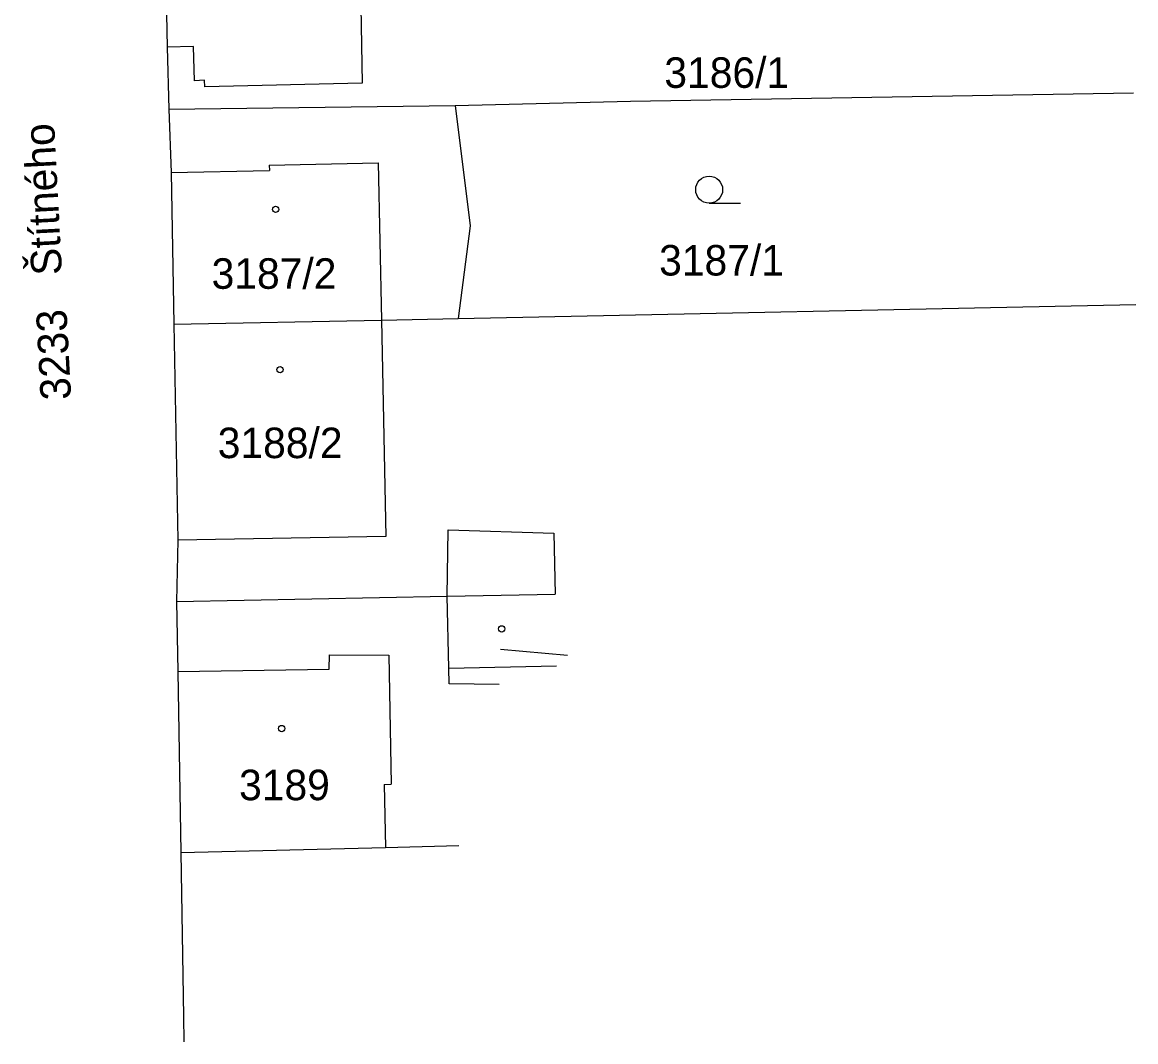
# Model space of a CAD drawing. Extents: x -738085 to -734306, y -1122197 to -1119753.
# Drawn here: x -734443.9 to -734381.9, y -1120299.5 to -1120242.7 of the extents above; entities that cross this region are included whole.
import ezdxf

# ---------------------------------------------------------------- set-up
doc = ezdxf.new("R2010")
doc.units = 0
for name, color, linetype in [('Hranice parcel', 7, 'Continuous'), ('Parcelní čísla', 7, 'Continuous'), ('Pop  PČ popisy', 7, 'Continuous'), ('Vnitřní kresba', 7, 'Continuous'), ('Značky budov', 7, 'Continuous'), ('Značky kultur', 7, 'Continuous')]:
    doc.layers.add(name, color=color, linetype=linetype)

msp = doc.modelspace()

# ---------------------------------------------------------------- linework, layer by layer
at = {"layer": 'Hranice parcel'}
for p, q in [((-734436.06, -1120234.59), (-734435.82, -1120244.07)), ((-734435.82, -1120244.07), (-734435.73, -1120247.52)), ((-734435.73, -1120247.52), (-734419.78, -1120247.33)), ((-734419.62, -1120259.19), (-734381.87, -1120258.4)), ((-734435.45, -1120259.5), (-734423.89, -1120259.28)), ((-734423.89, -1120259.28), (-734419.62, -1120259.19)), ((-734435.45, -1120259.5), (-734435.23, -1120271.53)), ((-734435.23, -1120271.53), (-734435.3, -1120274.95)), ((-734435.3, -1120274.95), (-734420.22, -1120274.65)), ((-734420.22, -1120274.65), (-734414.22, -1120274.53))]:
    msp.add_line(p, q, dxfattribs=at)
for points in [[(-734425.16, -1120234.37), (-734424.97, -1120246.07), (-734433.73, -1120246.29), (-734433.74, -1120245.92), (-734434.31, -1120245.94), (-734434.35, -1120244.04), (-734435.82, -1120244.07)], [(-734419.78, -1120247.33), (-734410.01, -1120247.08), (-734381.99, -1120246.61)], [(-734435.73, -1120247.52), (-734435.6, -1120251.05), (-734435.45, -1120259.5)], [(-734419.78, -1120247.33), (-734418.94, -1120254.02), (-734419.62, -1120259.19)], [(-734423.89, -1120259.28), (-734423.65, -1120271.32), (-734435.23, -1120271.53)], [(-734417.33, -1120279.57), (-734420.12, -1120279.52), (-734420.14, -1120278.65), (-734420.22, -1120274.65)], [(-734435.3, -1120274.95), (-734435.24, -1120278.84), (-734435.07, -1120288.93)], [(-734435.07, -1120288.93), (-734423.67, -1120288.65), (-734419.57, -1120288.53)], [(-734435.07, -1120288.93), (-734434.91, -1120298.05), (-734434.89, -1120299.46)]]:
    msp.add_lwpolyline(points, dxfattribs=at)
at = {"layer": 'Pop  PČ popisy'}
msp.add_line((-734417.26, -1120277.6), (-734413.53, -1120277.94), dxfattribs=at)
at = {"layer": 'Vnitřní kresba'}
for p, q in [((-734430.14, -1120250.64), (-734424.07, -1120250.52)), ((-734430.14, -1120250.64), (-734430.13, -1120250.94)), ((-734424.07, -1120250.52), (-734423.89, -1120259.28)), ((-734435.6, -1120251.05), (-734430.13, -1120250.94)), ((-734420.22, -1120274.65), (-734420.17, -1120270.95)), ((-734420.17, -1120270.95), (-734414.29, -1120271.14)), ((-734414.29, -1120271.14), (-734414.22, -1120274.53)), ((-734426.8, -1120278.71), (-734426.79, -1120277.91)), ((-734426.79, -1120277.91), (-734423.48, -1120277.94)), ((-734423.48, -1120277.94), (-734423.35, -1120285.12)), ((-734420.14, -1120278.65), (-734414.14, -1120278.53)), ((-734435.24, -1120278.84), (-734426.8, -1120278.71)), ((-734423.74, -1120285.13), (-734423.35, -1120285.12)), ((-734423.74, -1120285.13), (-734423.67, -1120288.65))]:
    msp.add_line(p, q, dxfattribs=at)
at = {"layer": 'Značky budov'}
for centre in [(-734429.787, -1120253.109), (-734429.537, -1120262.029), (-734417.187, -1120276.469), (-734429.447, -1120282.019)]:
    msp.add_circle(centre, 0.175, dxfattribs=at)
at = {"layer": 'Značky kultur'}
msp.add_line((-734405.633, -1120252.76), (-734403.883, -1120252.76), dxfattribs=at)
msp.add_circle((-734405.633, -1120252.01), 0.75, dxfattribs=at)

# ---------------------------------------------------------------- texts
at = {"layer": 'Parcelní čísla'}
for s, p in [('3186/1', (-734408.13, -1120246.34)), ('3187/1', (-734408.42, -1120256.79)), ('3187/2', (-734433.35, -1120257.53)), ('3188/2', (-734433.01, -1120266.96)), ('3189', (-734431.82, -1120286.01))]:
    msp.add_text(s, height=1.7, dxfattribs=at).set_placement(p)
msp.add_text('3233', height=1.7, rotation=93, dxfattribs=at).set_placement((-734441.171, -1120263.685))
at = {"layer": 'Pop  PČ popisy'}
msp.add_text('Štítného', height=1.7, rotation=93, dxfattribs=at).set_placement((-734441.681, -1120256.735))

doc.saveas('drawing.dxf')
